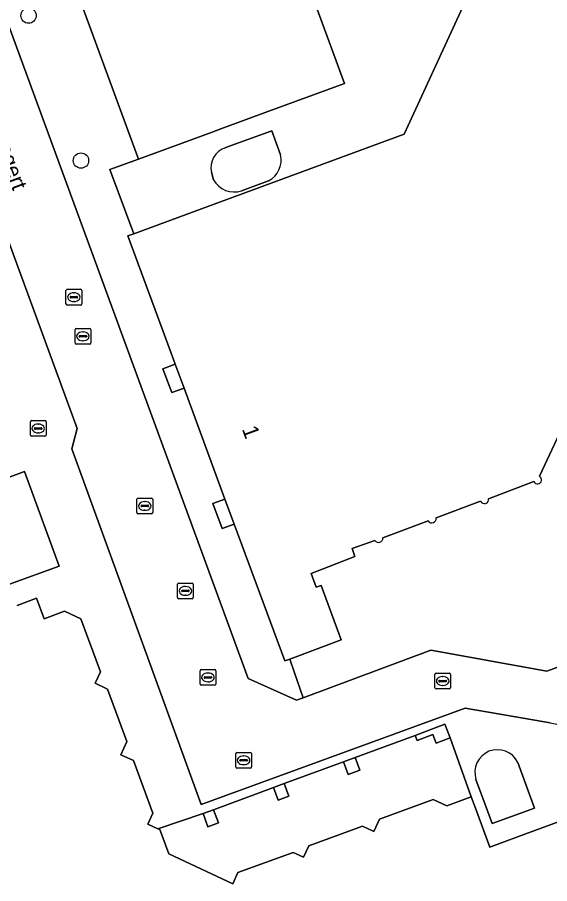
# Model space of a CAD drawing. Extents: x 160806 to 161707, y 383696 to 384148.
# Drawn here: x 160956.3 to 160990.2, y 383874.8 to 383930 of the extents above; entities that cross this region are included whole.
import ezdxf

# ---------------------------------------------------------------- set-up
doc = ezdxf.new("R2010")
doc.units = 0
for name, color, linetype in [('IMGEO_Boom', 7, 'Continuous'), ('IMGEO_Brandkraan', 7, 'Continuous'), ('IMGEO_Kolk', 7, 'Continuous'), ('IMGEO_Openbare_ruimte_label', 7, 'Continuous'), ('IMGEO_Pand', 7, 'Continuous'), ('IMGEO_Pand_nummerreeks', 7, 'Continuous'), ('IMGEO_Pand_overbouw', 7, 'Continuous'), ('IMGEO_Rijbaan_lokaal_open', 7, 'Continuous'), ('IMGEO_Rioolput', 7, 'Continuous'), ('IMGEO_Terreindeel_gesloten', 7, 'Continuous'), ('IMGEO_Voetpad_open', 7, 'Continuous')]:
    doc.layers.add(name, color=color, linetype=linetype)

msp = doc.modelspace()

# ---------------------------------------------------------------- linework, layer by layer
at = {"layer": 'IMGEO_Boom'}
for centre in [(160957.047, 383930.124), (160960.386, 383920.883)]:
    msp.add_circle(centre, 0.489, dxfattribs=at)
at = {"layer": 'IMGEO_Brandkraan'}
for p, q in [((160957.161, 383903.38), (160957.161, 383904.232)), ((160957.236, 383904.306), (160958.088, 383904.306)), ((160958.162, 383904.232), (160958.162, 383903.38)), ((160957.42, 383903.8), (160957.42, 383903.812)), ((160957.858, 383903.763), (160957.46, 383903.763)), ((160957.463, 383903.849), (160957.861, 383903.849)), ((160957.649, 383904.086), (160957.674, 383904.086)), ((160957.904, 383903.812), (160957.904, 383903.8)), ((160958.088, 383903.306), (160957.236, 383903.306)), ((160957.672, 383903.526), (160957.647, 383903.526))]:
    msp.add_line(p, q, dxfattribs=at)
for points in [[(160957.161, 383903.38), (160957.161, 383904.232)], [(160957.236, 383904.306), (160958.088, 383904.306)], [(160958.162, 383904.232), (160958.162, 383903.38)], [(160958.088, 383903.306), (160957.236, 383903.306)]]:
    msp.add_lwpolyline(points, dxfattribs=at)
for centre, radius, start, end in [((160957.238, 383904.23), 0.0765, 91.552, 178.448), ((160957.238, 383904.23), 0.0765, 91.552, 178.448), ((160958.086, 383904.23), 0.0765, 1.552, 88.448), ((160958.086, 383904.23), 0.0765, 1.552, 88.448), ((160957.46, 383903.809), 0.0403, 85.8775, 175.7526), ((160957.457, 383903.799), 0.0366, 178.938, 274.7102), ((160957.861, 383903.806), 0.043, 264.8664, 352.4533), ((160957.865, 383903.811), 0.0386, 1.7309, 96.639), ((160957.238, 383903.382), 0.0765, 181.552, 268.448), ((160957.238, 383903.382), 0.0765, 181.552, 268.448), ((160958.086, 383903.382), 0.0765, 271.552, 358.448), ((160958.086, 383903.382), 0.0765, 271.552, 358.448)]:
    msp.add_arc(centre, radius, start, end, dxfattribs=at)
for centre, major_axis, ratio, start_param, end_param in [((160957.648, 383903.806), (-0.387, 0.002), 0.722429, 4.712389, 7.853982), ((160957.673, 383903.806), (-0.39, 0.002), 0.717154, 1.570796, 4.712389)]:
    msp.add_ellipse(centre, major_axis=major_axis, ratio=ratio, start_param=start_param, end_param=end_param, dxfattribs=at)
at = {"layer": 'IMGEO_Kolk'}
for p, q in [((160960.006, 383909.256), (160960.006, 383910.108)), ((160960.081, 383910.182), (160960.933, 383910.182)), ((160960.494, 383909.962), (160960.519, 383909.962)), ((160961.007, 383910.108), (160961.007, 383909.256)), ((160960.933, 383909.182), (160960.081, 383909.182)), ((160960.265, 383909.676), (160960.265, 383909.688)), ((160960.703, 383909.639), (160960.305, 383909.639)), ((160960.308, 383909.725), (160960.706, 383909.725)), ((160960.517, 383909.402), (160960.492, 383909.402)), ((160960.749, 383909.688), (160960.749, 383909.676)), ((160963.952, 383898.443), (160963.952, 383899.295)), ((160964.027, 383899.369), (160964.879, 383899.369)), ((160964.953, 383899.295), (160964.953, 383898.443)), ((160964.211, 383898.863), (160964.211, 383898.875)), ((160964.649, 383898.826), (160964.251, 383898.826)), ((160964.254, 383898.912), (160964.652, 383898.912)), ((160964.44, 383899.149), (160964.465, 383899.149)), ((160964.695, 383898.875), (160964.695, 383898.863)), ((160964.879, 383898.369), (160964.027, 383898.369)), ((160964.463, 383898.589), (160964.438, 383898.589)), ((160967.974, 383887.51), (160967.974, 383888.362)), ((160968.049, 383888.436), (160968.901, 383888.436)), ((160968.462, 383888.216), (160968.487, 383888.216)), ((160968.975, 383888.362), (160968.975, 383887.51)), ((160983.006, 383888.207), (160983.858, 383888.207)), ((160968.233, 383887.93), (160968.233, 383887.942)), ((160968.671, 383887.893), (160968.273, 383887.893)), ((160968.276, 383887.979), (160968.674, 383887.979)), ((160968.485, 383887.656), (160968.46, 383887.656)), ((160968.717, 383887.942), (160968.717, 383887.93)), ((160982.931, 383887.281), (160982.931, 383888.133)), ((160983.19, 383887.701), (160983.19, 383887.713)), ((160983.628, 383887.664), (160983.23, 383887.664)), ((160983.233, 383887.75), (160983.631, 383887.75)), ((160983.419, 383887.987), (160983.444, 383887.987)), ((160983.674, 383887.713), (160983.674, 383887.701)), ((160983.932, 383888.133), (160983.932, 383887.281)), ((160968.901, 383887.436), (160968.049, 383887.436)), ((160983.858, 383887.207), (160983.006, 383887.207)), ((160983.442, 383887.427), (160983.417, 383887.427))]:
    msp.add_line(p, q, dxfattribs=at)
for points in [[(160960.006, 383909.256), (160960.006, 383910.108)], [(160960.081, 383910.182), (160960.933, 383910.182)], [(160961.007, 383910.108), (160961.007, 383909.256)], [(160960.933, 383909.182), (160960.081, 383909.182)], [(160963.952, 383898.443), (160963.952, 383899.295)], [(160964.027, 383899.369), (160964.879, 383899.369)], [(160964.953, 383899.295), (160964.953, 383898.443)], [(160964.879, 383898.369), (160964.027, 383898.369)], [(160967.974, 383887.51), (160967.974, 383888.362)], [(160968.049, 383888.436), (160968.901, 383888.436)], [(160968.975, 383888.362), (160968.975, 383887.51)], [(160983.006, 383888.207), (160983.858, 383888.207)], [(160982.931, 383887.281), (160982.931, 383888.133)], [(160983.932, 383888.133), (160983.932, 383887.281)], [(160968.901, 383887.436), (160968.049, 383887.436)], [(160983.858, 383887.207), (160983.006, 383887.207)]]:
    msp.add_lwpolyline(points, dxfattribs=at)
for centre, radius, start, end in [((160960.083, 383910.106), 0.0765, 91.552, 178.448), ((160960.083, 383910.106), 0.0765, 91.552, 178.448), ((160960.931, 383910.106), 0.0765, 1.552, 88.448), ((160960.931, 383910.106), 0.0765, 1.552, 88.448), ((160960.083, 383909.258), 0.0765, 181.552, 268.448), ((160960.083, 383909.258), 0.0765, 181.552, 268.448), ((160960.305, 383909.685), 0.0403, 85.8775, 175.7526), ((160960.302, 383909.675), 0.0366, 178.938, 274.7102), ((160960.706, 383909.682), 0.043, 264.8664, 352.4533), ((160960.71, 383909.687), 0.0386, 1.7309, 96.639), ((160960.931, 383909.258), 0.0765, 271.552, 358.448), ((160960.931, 383909.258), 0.0765, 271.552, 358.448), ((160964.029, 383899.293), 0.0765, 91.552, 178.448), ((160964.029, 383899.293), 0.0765, 91.552, 178.448), ((160964.877, 383899.293), 0.0765, 1.552, 88.448), ((160964.877, 383899.293), 0.0765, 1.552, 88.448), ((160964.251, 383898.872), 0.0403, 85.8775, 175.7526), ((160964.248, 383898.862), 0.0366, 178.938, 274.7102), ((160964.652, 383898.869), 0.043, 264.8664, 352.4533), ((160964.656, 383898.874), 0.0386, 1.7309, 96.639), ((160964.029, 383898.445), 0.0765, 181.552, 268.448), ((160964.029, 383898.445), 0.0765, 181.552, 268.448), ((160964.877, 383898.445), 0.0765, 271.552, 358.448), ((160964.877, 383898.445), 0.0765, 271.552, 358.448), ((160968.051, 383888.36), 0.0765, 91.552, 178.448), ((160968.051, 383888.36), 0.0765, 91.552, 178.448), ((160968.899, 383888.36), 0.0765, 1.552, 88.448), ((160968.899, 383888.36), 0.0765, 1.552, 88.448), ((160983.008, 383888.131), 0.0765, 91.552, 178.448), ((160983.008, 383888.131), 0.0765, 91.552, 178.448), ((160983.856, 383888.131), 0.0765, 1.552, 88.448), ((160983.856, 383888.131), 0.0765, 1.552, 88.448), ((160968.273, 383887.939), 0.0403, 85.8775, 175.7526), ((160968.27, 383887.929), 0.0366, 178.938, 274.7102), ((160968.674, 383887.936), 0.043, 264.8664, 352.4533), ((160968.678, 383887.941), 0.0386, 1.7309, 96.639), ((160983.23, 383887.71), 0.0403, 85.8775, 175.7526), ((160983.227, 383887.7), 0.0366, 178.938, 274.7102), ((160983.631, 383887.707), 0.043, 264.8664, 352.4533), ((160983.635, 383887.712), 0.0386, 1.7309, 96.639), ((160968.051, 383887.512), 0.0765, 181.552, 268.448), ((160968.051, 383887.512), 0.0765, 181.552, 268.448), ((160968.899, 383887.512), 0.0765, 271.552, 358.448), ((160968.899, 383887.512), 0.0765, 271.552, 358.448), ((160983.008, 383887.283), 0.0765, 181.552, 268.448), ((160983.008, 383887.283), 0.0765, 181.552, 268.448), ((160983.856, 383887.283), 0.0765, 271.552, 358.448), ((160983.856, 383887.283), 0.0765, 271.552, 358.448)]:
    msp.add_arc(centre, radius, start, end, dxfattribs=at)
for centre, major_axis, ratio, start_param, end_param in [((160960.493, 383909.682), (-0.387, 0.002), 0.722429, 4.712389, 7.853982), ((160960.518, 383909.682), (-0.39, 0.002), 0.717154, 1.570796, 4.712389), ((160964.439, 383898.869), (-0.387, 0.002), 0.722429, 4.712389, 7.853982), ((160964.464, 383898.869), (-0.39, 0.002), 0.717154, 1.570796, 4.712389), ((160968.461, 383887.936), (-0.387, 0.002), 0.722429, 4.712389, 7.853982), ((160968.486, 383887.936), (-0.39, 0.002), 0.717154, 1.570796, 4.712389), ((160983.418, 383887.707), (-0.387, 0.002), 0.722429, 4.712389, 7.853982), ((160983.443, 383887.707), (-0.39, 0.002), 0.717154, 1.570796, 4.712389)]:
    msp.add_ellipse(centre, major_axis=major_axis, ratio=ratio, start_param=start_param, end_param=end_param, dxfattribs=at)
at = {"layer": 'IMGEO_Pand'}
for points in [[(160956.293, 383942.096), (160964.049, 383920.98), (160968.743, 383922.704), (160969.3, 383922.908), (160972.116, 383923.943), (160977.173, 383925.8), (160969.36, 383947.074)], [(160990.19, 383942.611), (160980.975, 383922.577), (160968.062, 383917.812), (160963.751, 383916.221), (160963.371, 383916.081), (160966.281, 383908.197), (160966.389, 383907.903), (160966.95, 383906.383), (160969.561, 383899.31), (160970.15, 383897.715), (160973.37, 383888.99), (160973.686, 383889.108), (160976.952, 383890.328), (160975.687, 383893.788), (160975.371, 383893.69), (160975.05, 383894.563), (160977.84, 383895.636), (160977.662, 383896.151), (160979.104, 383896.674)], [(160973.107, 383921.247), (160972.541, 383922.786), (160969.724, 383921.754), (160969.576, 383921.7)], [(160968.697, 383920.138), (160968.834, 383919.66)], [(160970.613, 383918.956), (160972.334, 383919.588)], [(160989.606, 383900.762), (160991.657, 383905.16)], [(160955.83, 383893.878), (160958.991, 383895.039), (160956.781, 383901.058), (160953.618, 383899.896)], [(160986.352, 383899.331), (160989.233, 383900.425)], [(160983.003, 383898.105), (160985.842, 383899.173)], [(160979.624, 383896.845), (160982.509, 383897.914)], [(160991.559, 383879.009), (160988.268, 383877.801), (160986.425, 383877.124), (160985.512, 383879.611), (160985.251, 383880.322), (160983.694, 383879.75), (160982.817, 383880.156), (160979.408, 383878.905), (160979.043, 383878.115), (160978.314, 383878.452), (160974.904, 383877.2), (160974.572, 383876.482), (160973.913, 383876.786), (160970.387, 383875.492), (160970.062, 383874.789), (160965.973, 383876.682), (160965.403, 383878.234), (160965.28, 383878.291), (160964.635, 383878.589), (160964.957, 383879.283), (160963.726, 383882.635), (160962.916, 383883.01), (160963.309, 383883.858), (160962.084, 383887.193), (160961.29, 383887.56), (160961.624, 383888.283), (160960.382, 383891.667), (160959.339, 383892.15), (160958.04, 383891.673), (160957.559, 383892.984), (160956.324, 383892.531)], [(160985.549, 383881.437), (160986.135, 383879.839), (160986.583, 383878.619), (160987.803, 383879.067), (160989.284, 383879.611), (160988.217, 383882.517)]]:
    msp.add_lwpolyline(points, dxfattribs=at)
for points in [[(160982.801, 383884.293), (160983.006, 383883.747), (160983.899, 383884.082), (160983.573, 383884.95), (160981.685, 383884.242), (160981.806, 383883.919)], [(160977.843, 383882.826), (160977.115, 383882.553), (160977.417, 383881.746), (160978.146, 383882.019)], [(160973.326, 383881.166), (160972.645, 383880.91), (160972.947, 383880.105), (160973.628, 383880.361)], [(160968.826, 383879.503), (160968.16, 383879.253), (160968.473, 383878.417), (160969.14, 383878.667)]]:
    msp.add_lwpolyline(points, close=True, dxfattribs=at)
for centre, radius, start, end in [((160970.009, 383920.428), 1.344, 108.7966, 192.4669), ((160971.634, 383920.924), 1.508, 297.66, 12.3743), ((160970.146, 383920.375), 1.494, 208.6063, 288.2135), ((160989.47, 383900.538), 0.262, 205.4142, 58.7805), ((160986.087, 383899.284), 0.269, 204.3448, 10.0816), ((160982.739, 383898.054), 0.269, 211.3304, 10.9465), ((160979.346, 383896.815), 0.28, 210.2325, 6.174), ((160986.919, 383881.889), 1.442, 25.801, 198.2749)]:
    msp.add_arc(centre, radius, start, end, dxfattribs=at)
at = {"layer": 'IMGEO_Pand_overbouw'}
msp.add_lwpolyline([(160983.899, 383884.082), (160983.006, 383883.747), (160982.801, 383884.293), (160981.806, 383883.919), (160981.685, 383884.242), (160977.843, 383882.826), (160978.146, 383882.019), (160977.417, 383881.746), (160977.115, 383882.553), (160973.326, 383881.166), (160973.628, 383880.361), (160972.947, 383880.105), (160972.645, 383880.91), (160968.826, 383879.503), (160969.14, 383878.667), (160968.473, 383878.417), (160968.16, 383879.253), (160965.28, 383878.291), (160965.403, 383878.234), (160965.973, 383876.682), (160970.062, 383874.789), (160970.387, 383875.492), (160973.913, 383876.786), (160974.572, 383876.482), (160974.904, 383877.2), (160978.314, 383878.452), (160979.043, 383878.115), (160979.408, 383878.905), (160982.817, 383880.156), (160983.694, 383879.75), (160985.251, 383880.322)], close=True, dxfattribs=at)
at = {"layer": 'IMGEO_Rijbaan_lokaal_open'}
msp.add_lwpolyline([(160943.158, 383950.097), (160950.161, 383931.007), (160960.137, 383903.811), (160959.806, 383902.516), (160968.05, 383879.828), (160984.869, 383885.974), (160986.341, 383885.715), (160990.275, 383885.032), (160991.432, 383884.817), (161000, 383887.972), (161034.783, 383900.781), (161033.437, 383904.394), (161000, 383892.005), (160990.074, 383888.326), (160982.677, 383889.672), (160974.531, 383886.634), (160974.125, 383886.483), (160971.037, 383887.859), (160947.548, 383951.917), (160947.428, 383954.476), (160941.963, 383951.859)], close=True, dxfattribs=at)
at = {"layer": 'IMGEO_Rioolput'}
for p, q in [((160959.431, 383911.75), (160959.431, 383912.602)), ((160959.506, 383912.676), (160960.358, 383912.676)), ((160960.432, 383912.602), (160960.432, 383911.75)), ((160959.69, 383912.17), (160959.69, 383912.182)), ((160960.128, 383912.133), (160959.73, 383912.133)), ((160959.733, 383912.219), (160960.131, 383912.219)), ((160959.919, 383912.456), (160959.944, 383912.456)), ((160960.174, 383912.182), (160960.174, 383912.17)), ((160960.358, 383911.676), (160959.506, 383911.676)), ((160959.942, 383911.896), (160959.917, 383911.896)), ((160966.54, 383893.026), (160966.54, 383893.878)), ((160966.615, 383893.952), (160967.467, 383893.952)), ((160967.028, 383893.732), (160967.053, 383893.732)), ((160967.541, 383893.878), (160967.541, 383893.026)), ((160966.799, 383893.446), (160966.799, 383893.458)), ((160967.237, 383893.409), (160966.839, 383893.409)), ((160966.842, 383893.495), (160967.24, 383893.495)), ((160967.051, 383893.172), (160967.026, 383893.172)), ((160967.283, 383893.458), (160967.283, 383893.446)), ((160967.467, 383892.952), (160966.615, 383892.952)), ((160970.244, 383882.229), (160970.244, 383883.081)), ((160970.319, 383883.155), (160971.171, 383883.155)), ((160970.546, 383882.698), (160970.944, 383882.698)), ((160970.732, 383882.935), (160970.757, 383882.935)), ((160971.245, 383883.081), (160971.245, 383882.229)), ((160971.171, 383882.155), (160970.319, 383882.155)), ((160970.503, 383882.649), (160970.503, 383882.661)), ((160970.941, 383882.612), (160970.543, 383882.612)), ((160970.755, 383882.375), (160970.73, 383882.375)), ((160970.987, 383882.661), (160970.987, 383882.649))]:
    msp.add_line(p, q, dxfattribs=at)
for points in [[(160959.431, 383911.75), (160959.431, 383912.602)], [(160959.506, 383912.676), (160960.358, 383912.676)], [(160960.432, 383912.602), (160960.432, 383911.75)], [(160960.358, 383911.676), (160959.506, 383911.676)], [(160966.54, 383893.026), (160966.54, 383893.878)], [(160966.615, 383893.952), (160967.467, 383893.952)], [(160967.541, 383893.878), (160967.541, 383893.026)], [(160967.467, 383892.952), (160966.615, 383892.952)], [(160970.244, 383882.229), (160970.244, 383883.081)], [(160970.319, 383883.155), (160971.171, 383883.155)], [(160971.245, 383883.081), (160971.245, 383882.229)], [(160971.171, 383882.155), (160970.319, 383882.155)]]:
    msp.add_lwpolyline(points, dxfattribs=at)
for centre, radius, start, end in [((160959.508, 383912.6), 0.0765, 91.552, 178.448), ((160959.508, 383912.6), 0.0765, 91.552, 178.448), ((160960.356, 383912.6), 0.0765, 1.552, 88.448), ((160960.356, 383912.6), 0.0765, 1.552, 88.448), ((160959.73, 383912.179), 0.0403, 85.8775, 175.7526), ((160959.727, 383912.169), 0.0366, 178.938, 274.7102), ((160960.131, 383912.176), 0.043, 264.8664, 352.4533), ((160960.135, 383912.181), 0.0386, 1.7309, 96.639), ((160959.508, 383911.752), 0.0765, 181.552, 268.448), ((160959.508, 383911.752), 0.0765, 181.552, 268.448), ((160960.356, 383911.752), 0.0765, 271.552, 358.448), ((160960.356, 383911.752), 0.0765, 271.552, 358.448), ((160966.617, 383893.876), 0.0765, 91.552, 178.448), ((160966.617, 383893.876), 0.0765, 91.552, 178.448), ((160967.465, 383893.876), 0.0765, 1.552, 88.448), ((160967.465, 383893.876), 0.0765, 1.552, 88.448), ((160966.839, 383893.455), 0.0403, 85.8775, 175.7526), ((160966.836, 383893.445), 0.0366, 178.938, 274.7102), ((160967.24, 383893.452), 0.043, 264.8664, 352.4533), ((160967.244, 383893.457), 0.0386, 1.7309, 96.639), ((160966.617, 383893.028), 0.0765, 181.552, 268.448), ((160966.617, 383893.028), 0.0765, 181.552, 268.448), ((160967.465, 383893.028), 0.0765, 271.552, 358.448), ((160967.465, 383893.028), 0.0765, 271.552, 358.448), ((160970.321, 383883.079), 0.0765, 91.552, 178.448), ((160970.321, 383883.079), 0.0765, 91.552, 178.448), ((160970.543, 383882.658), 0.0403, 85.8775, 175.7526), ((160970.948, 383882.66), 0.0386, 1.7309, 96.639), ((160971.169, 383883.079), 0.0765, 1.552, 88.448), ((160971.169, 383883.079), 0.0765, 1.552, 88.448), ((160970.321, 383882.231), 0.0765, 181.552, 268.448), ((160970.321, 383882.231), 0.0765, 181.552, 268.448), ((160970.54, 383882.648), 0.0366, 178.938, 274.7102), ((160970.944, 383882.655), 0.043, 264.8664, 352.4533), ((160971.169, 383882.231), 0.0765, 271.552, 358.448), ((160971.169, 383882.231), 0.0765, 271.552, 358.448)]:
    msp.add_arc(centre, radius, start, end, dxfattribs=at)
for centre, major_axis, ratio, start_param, end_param in [((160959.918, 383912.176), (-0.387, 0.002), 0.722429, 4.712389, 7.853982), ((160959.943, 383912.176), (-0.39, 0.002), 0.717154, 1.570796, 4.712389), ((160967.027, 383893.452), (-0.387, 0.002), 0.722429, 4.712389, 7.853982), ((160967.052, 383893.452), (-0.39, 0.002), 0.717154, 1.570796, 4.712389), ((160970.731, 383882.655), (-0.387, 0.002), 0.722429, 4.712389, 7.853982), ((160970.756, 383882.655), (-0.39, 0.002), 0.717154, 1.570796, 4.712389)]:
    msp.add_ellipse(centre, major_axis=major_axis, ratio=ratio, start_param=start_param, end_param=end_param, dxfattribs=at)
at = {"layer": 'IMGEO_Terreindeel_gesloten'}
for points in [[(160969.36, 383947.074), (160977.173, 383925.8), (160972.116, 383923.943), (160969.3, 383922.908), (160968.743, 383922.704), (160964.049, 383920.98), (160962.214, 383920.319), (160963.751, 383916.221), (160968.062, 383917.812), (160980.975, 383922.577), (160990.19, 383942.611)], [(160969.576, 383921.7), (160969.724, 383921.754), (160972.541, 383922.786), (160973.107, 383921.247)], [(160968.834, 383919.66), (160968.697, 383920.138)], [(160972.334, 383919.588), (160970.613, 383918.956)], [(160991.657, 383905.16), (160989.606, 383900.762)], [(160989.233, 383900.425), (160986.352, 383899.331)], [(160985.842, 383899.173), (160983.003, 383898.105)], [(160982.509, 383897.914), (160979.624, 383896.845)], [(160979.104, 383896.674), (160977.662, 383896.151), (160977.84, 383895.636), (160975.05, 383894.563), (160975.371, 383893.69), (160975.687, 383893.788), (160976.952, 383890.328), (160973.686, 383889.108), (160973.964, 383888.294), (160974.531, 383886.634), (160982.677, 383889.672), (160990.074, 383888.326), (161000, 383892.005)]]:
    msp.add_lwpolyline(points, dxfattribs=at)
for centre, radius, start, end in [((160970.009, 383920.428), 1.344, 108.7966, 192.4669), ((160971.634, 383920.924), 1.508, 297.66, 12.3743), ((160970.146, 383920.375), 1.494, 208.6063, 288.2135), ((160989.47, 383900.538), 0.262, 205.4142, 58.7805), ((160986.087, 383899.284), 0.269, 204.3448, 10.0816), ((160982.739, 383898.054), 0.269, 211.3304, 10.9465), ((160979.346, 383896.815), 0.28, 210.2325, 6.174)]:
    msp.add_arc(centre, radius, start, end, dxfattribs=at)
at = {"layer": 'IMGEO_Voetpad_open'}
for points in [[(160947.548, 383951.917), (160971.037, 383887.859), (160974.125, 383886.483), (160974.531, 383886.634), (160973.964, 383888.294), (160973.686, 383889.108), (160973.37, 383888.99), (160970.15, 383897.715), (160969.371, 383897.428), (160968.781, 383899.023), (160969.561, 383899.31), (160966.95, 383906.383), (160966.166, 383906.094), (160965.605, 383907.614), (160966.389, 383907.903), (160966.281, 383908.197), (160963.371, 383916.081), (160963.751, 383916.221), (160962.214, 383920.319), (160964.049, 383920.98), (160956.293, 383942.096)], [(160990.275, 383885.032), (160986.341, 383885.715), (160984.869, 383885.974), (160968.05, 383879.828), (160959.806, 383902.516), (160960.137, 383903.811), (160950.161, 383931.007)], [(160953.618, 383899.896), (160956.781, 383901.058), (160958.991, 383895.039), (160955.83, 383893.878)], [(160956.324, 383892.531), (160957.559, 383892.984), (160958.04, 383891.673), (160959.339, 383892.15), (160960.382, 383891.667), (160961.624, 383888.283), (160961.29, 383887.56), (160962.084, 383887.193), (160963.309, 383883.858), (160962.916, 383883.01), (160963.726, 383882.635), (160964.957, 383879.283), (160964.635, 383878.589), (160965.28, 383878.291), (160968.16, 383879.253), (160968.826, 383879.503), (160972.645, 383880.91), (160973.326, 383881.166), (160977.115, 383882.553), (160977.843, 383882.826), (160981.685, 383884.242), (160983.573, 383884.95), (160983.899, 383884.082), (160985.251, 383880.322)], [(160988.217, 383882.517), (160989.284, 383879.611), (160987.803, 383879.067), (160986.583, 383878.619), (160986.135, 383879.839), (160985.549, 383881.437)], [(160985.251, 383880.322), (160985.512, 383879.611), (160986.425, 383877.124), (160988.268, 383877.801), (160991.559, 383879.009)]]:
    msp.add_lwpolyline(points, dxfattribs=at)
for points in [[(160966.389, 383907.903), (160965.605, 383907.614), (160966.166, 383906.094), (160966.95, 383906.383)], [(160969.561, 383899.31), (160968.781, 383899.023), (160969.371, 383897.428), (160970.15, 383897.715)], [(160983.899, 383884.082), (160983.006, 383883.747), (160982.801, 383884.293), (160981.806, 383883.919), (160981.685, 383884.242), (160977.843, 383882.826), (160978.146, 383882.019), (160977.417, 383881.746), (160977.115, 383882.553), (160973.326, 383881.166), (160973.628, 383880.361), (160972.947, 383880.105), (160972.645, 383880.91), (160968.826, 383879.503), (160969.14, 383878.667), (160968.473, 383878.417), (160968.16, 383879.253), (160965.28, 383878.291), (160965.403, 383878.234), (160965.973, 383876.682), (160970.062, 383874.789), (160970.387, 383875.492), (160973.913, 383876.786), (160974.572, 383876.482), (160974.904, 383877.2), (160978.314, 383878.452), (160979.043, 383878.115), (160979.408, 383878.905), (160982.817, 383880.156), (160983.694, 383879.75), (160985.251, 383880.322)]]:
    msp.add_lwpolyline(points, close=True, dxfattribs=at)
msp.add_arc((160986.919, 383881.889), 1.442, 25.801, 198.2749, dxfattribs=at)

# ---------------------------------------------------------------- texts
at = {"layer": 'IMGEO_Openbare_ruimte_label'}
msp.add_text('Bogert', height=1, rotation=290.1202, dxfattribs=at).set_placement((160954.705, 383922.619))
at = {"layer": 'IMGEO_Pand_nummerreeks'}
msp.add_text('1', height=1, rotation=290.2455, dxfattribs=at).set_placement((160970.629, 383903.77))

doc.saveas('drawing.dxf')
